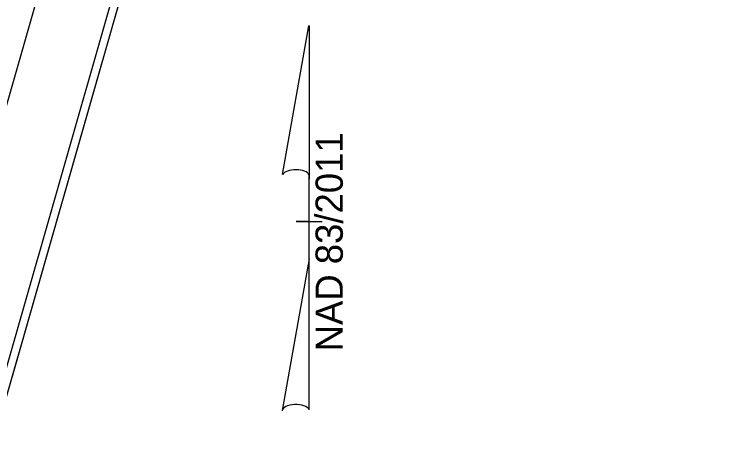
# Model space of a CAD drawing. Extents: x 2096988 to 2098509, y 687711 to 689775.
# Drawn here: x 2097368.1 to 2097587.9, y 689227.7 to 689361.6 of the extents above; entities that cross this region are included whole.
import ezdxf

# ---------------------------------------------------------------- set-up
doc = ezdxf.new("R2010")
doc.units = 0
for name, color, linetype in [('Prop North Arrow NAD83 for Plan Sheets CELL', 7, 'Continuous'), ('Sheet Layout Plan Border', 7, 'Continuous'), ('Sheet Plot Border Inside CELL', 7, 'Continuous'), ('Sheet Plot Border Outside CELL', 7, 'Continuous'), ('Sheet Profile CELL', 7, 'Continuous')]:
    doc.layers.add(name, color=color, linetype=linetype)

msp = doc.modelspace()

# ---------------------------------------------------------------- linework, layer by layer
at = {"layer": 'Prop North Arrow NAD83 for Plan Sheets CELL'}
for p, q in [((2097451.81, 689311.62), (2097460.01, 689357.97)), ((2097460.06, 689357.97), (2097460.01, 689357.97)), ((2097460.06, 689357.97), (2097460.01, 689357.97)), ((2097460.06, 689357.97), (2097460.06, 689310.17)), ((2097460.06, 689285.37), (2097460.06, 689311.57)), ((2097460.06, 689310.17), (2097460.06, 689311.52)), ((2097456.06, 689296.97), (2097456.01, 689296.97)), ((2097459.61, 689296.97), (2097456.06, 689296.97)), ((2097456.11, 689296.97), (2097464.11, 689296.97)), ((2097460.06, 689285.37), (2097451.71, 689238.12)), ((2097460.11, 689238.32), (2097460.06, 689285.37))]:
    msp.add_line(p, q, dxfattribs=at)
for centre, start_param, end_param in [((2097455.95, 689311.13), 0.216388, 2.908219), ((2097455.95, 689237.96), 0.201328, 3.141593)]:
    msp.add_ellipse(centre, major_axis=(4.23, -0.03), ratio=0.461098, start_param=start_param, end_param=end_param, dxfattribs=at)
at = {"layer": 'Sheet Layout Plan Border'}
msp.add_lwpolyline([(2098117.8, 688054.49), (2097347.73, 688084.03), (2097057.83, 688167.01), (2097415.58, 689416.76), (2097595.66, 689365.22), (2097650.71, 689557.55), (2098480.09, 689320.13)], close=True, dxfattribs=at)
at = {"layer": 'Sheet Plot Border Inside CELL'}
msp.add_lwpolyline([(2098027.36, 687729.29), (2098485.98, 689331.44), (2097471.62, 689621.81), (2097013, 688019.66)], close=True, dxfattribs=at)
at = {"layer": 'Sheet Plot Border Outside CELL'}
msp.add_lwpolyline([(2098045.36, 687710.62), (2098508.8, 689329.59), (2097451.28, 689632.31), (2096987.84, 688013.34)], close=True, dxfattribs=at)
at = {"layer": 'Sheet Profile CELL'}
msp.add_lwpolyline([(2097470.64, 689609.09), (2097057.83, 688167.01), (2098067.29, 687878.05), (2098480.09, 689320.13)], close=True, dxfattribs=at)

# ---------------------------------------------------------------- texts
at = {"layer": 'Prop North Arrow NAD83 for Plan Sheets CELL'}
msp.add_text('NAD 83/2011', height=8.5, rotation=90, dxfattribs=at).set_placement((2097470.58, 689256.5))

doc.saveas('drawing.dxf')
